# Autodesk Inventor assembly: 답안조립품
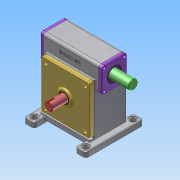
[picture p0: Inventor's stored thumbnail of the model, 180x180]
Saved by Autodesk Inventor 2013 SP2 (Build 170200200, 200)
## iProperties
Created: 2025-06
Part Number: 답안조립품
Document SubType Name: Assembly
Designer: a
Author: a
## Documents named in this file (11)
- C:\Users\a\Desktop\750603V1005\답안조립품.iam
- C:\Users\a\Desktop\750603V1005\본체.ipt
- C:\Users\a\Desktop\750603V1005\깊은 홈 볼 베어링 6209.ipt
- C:\Users\a\Desktop\750603V1005\뒷커버.ipt
- C:\Users\a\Desktop\750603V1005\앞커버.ipt
- C:\Users\a\Desktop\750603V1005\웜 샤프트.ipt
- C:\Users\a\Desktop\750603V1005\오일 실 35 55 11.ipt
- C:\Users\a\Desktop\750603V1005\오일 실 30 42 7.ipt
- C:\Users\a\Desktop\750603V1005\웜 휠 커버.ipt
- C:\Users\a\Desktop\750603V1005\웜 휠.ipt
- C:\Users\a\Desktop\750603V1005\깊은 홈 볼 베어링 6206.ipt
